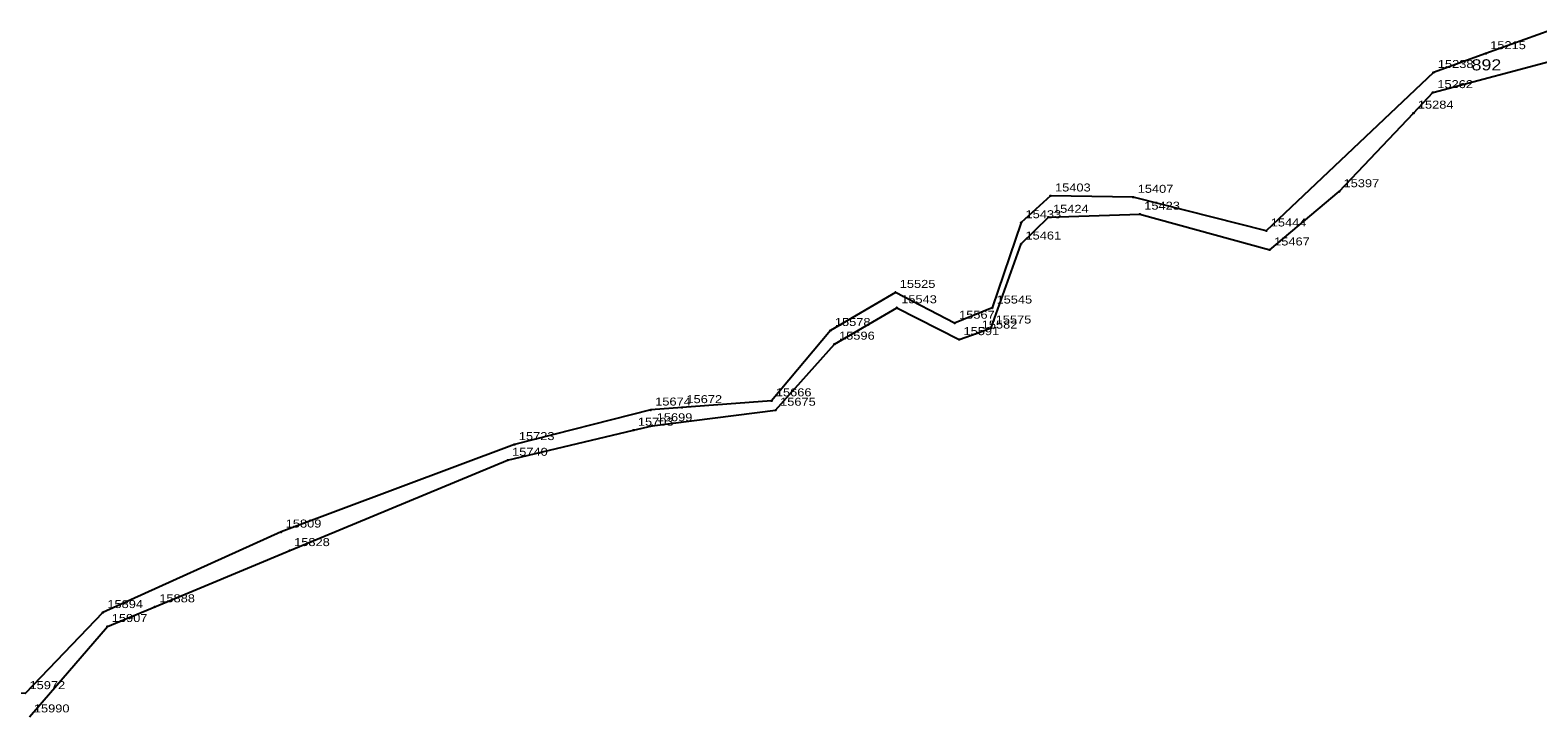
# Model space of a CAD drawing. Extents: x 4640203 to 4641683, y 5358965 to 5360242.
# Drawn here: x 4641223.1 to 4641393, y 5359721.3 to 5359798.7 of the extents above; entities that cross this region are included whole.
import ezdxf

# ---------------------------------------------------------------- set-up
doc = ezdxf.new("R2010")
doc.units = 0
doc.header["$LTSCALE"] = 0.36
doc.layers.add('24', color=7, linetype='Continuous')
for name, color, linetype, lineweight in [('25', 7, 'Continuous', 25), ('27', 7, 'Continuous', 25), ('8', 7, 'Continuous', 25)]:
    doc.layers.add(name, color=color, linetype=linetype, lineweight=lineweight)

msp = doc.modelspace()

# ---------------------------------------------------------------- linework, layer by layer
at = {"layer": '25'}
for points in [[(4641394.42, 5359798.68), (4641387.1, 5359796.04), (4641381.2, 5359793.92), (4641362.38, 5359776.07), (4641347.39, 5359779.86), (4641338.08, 5359780.01), (4641334.76, 5359777), (4641331.49, 5359767.39), (4641327.27, 5359765.68), (4641320.59, 5359769.15), (4641313.28, 5359764.86), (4641306.63, 5359756.94), (4641296.56, 5359756.17), (4641293.04, 5359755.9), (4641277.68, 5359752.01), (4641251.42, 5359742.16), (4641231.33, 5359733.09), (4641222.56, 5359723.96), (4641218.63, 5359724.05), (4641212.42, 5359727.51), (4641209.43, 5359728.75), (4641205.11, 5359734.45), (4641198.05, 5359737.91)], [(4641362.76, 5359773.93), (4641370.58, 5359780.49), (4641378.95, 5359789.34), (4641381.14, 5359791.65), (4641395.53, 5359795.47)], [(4641223.05, 5359721.34), (4641231.83, 5359731.52), (4641237.18, 5359733.74), (4641252.37, 5359740.07), (4641276.92, 5359750.24), (4641291.09, 5359753.63), (4641293.21, 5359754.13), (4641307.11, 5359755.88), (4641313.75, 5359763.32), (4641320.75, 5359767.42), (4641327.77, 5359763.83), (4641329.82, 5359764.57), (4641331.39, 5359765.14), (4641334.75, 5359774.6), (4641337.85, 5359777.61), (4641348.13, 5359777.96), (4641362.76, 5359773.93)]]:
    msp.add_lwpolyline(points, dxfattribs=at)
at = {"layer": '27'}
for points in [[(4641394.42, 5359798.68), (4641387.1, 5359796.04), (4641381.2, 5359793.92), (4641362.38, 5359776.07), (4641347.39, 5359779.86), (4641338.08, 5359780.01), (4641334.76, 5359777), (4641331.49, 5359767.39), (4641327.27, 5359765.68), (4641320.59, 5359769.15), (4641313.28, 5359764.86), (4641306.63, 5359756.94), (4641296.56, 5359756.17), (4641293.04, 5359755.9), (4641277.68, 5359752.01), (4641251.42, 5359742.16), (4641231.33, 5359733.09), (4641222.56, 5359723.96)], [(4641348.13, 5359777.96), (4641362.76, 5359773.93), (4641370.58, 5359780.49), (4641378.95, 5359789.34), (4641381.14, 5359791.65), (4641395.53, 5359795.47)], [(4641223.05, 5359721.34), (4641231.83, 5359731.52), (4641237.18, 5359733.74), (4641252.37, 5359740.07), (4641276.92, 5359750.24), (4641291.09, 5359753.63), (4641293.21, 5359754.13), (4641307.11, 5359755.88), (4641313.75, 5359763.32), (4641320.75, 5359767.42), (4641327.77, 5359763.83), (4641329.82, 5359764.57), (4641331.39, 5359765.14), (4641334.75, 5359774.6), (4641337.85, 5359777.61), (4641348.13, 5359777.96)]]:
    msp.add_lwpolyline(points, dxfattribs=at)
at = {"layer": '8'}
for centre in [(4641387.1, 5359796.04), (4641381.2, 5359793.92), (4641381.14, 5359791.65), (4641378.95, 5359789.34), (4641338.08, 5359780.01), (4641370.58, 5359780.49), (4641347.39, 5359779.86), (4641334.76, 5359777), (4641337.85, 5359777.61), (4641348.13, 5359777.96), (4641362.38, 5359776.07), (4641334.75, 5359774.6), (4641362.76, 5359773.93), (4641320.59, 5359769.15), (4641320.75, 5359767.42), (4641331.49, 5359767.39), (4641313.28, 5359764.86), (4641327.27, 5359765.68), (4641331.39, 5359765.14), (4641313.75, 5359763.32), (4641327.77, 5359763.83), (4641329.82, 5359764.57), (4641296.56, 5359756.17), (4641306.63, 5359756.94), (4641293.04, 5359755.9), (4641307.11, 5359755.88), (4641291.09, 5359753.63), (4641293.21, 5359754.13), (4641277.68, 5359752.01), (4641276.92, 5359750.24), (4641251.42, 5359742.16), (4641252.37, 5359740.07), (4641231.33, 5359733.09), (4641237.18, 5359733.74), (4641231.83, 5359731.52)]:
    msp.add_circle(centre, 0.045, dxfattribs=at)

# ---------------------------------------------------------------- texts
at = {"layer": '24', "width": 1.2}
msp.add_text('892', height=1.25, dxfattribs=at).set_placement((4641385.5, 5359794.15))
at = {"layer": '8', "width": 1.2}
for s, p in [('15215', (4641387.6, 5359796.54)), ('15238', (4641381.7, 5359794.42)), ('15262', (4641381.64, 5359792.15)), ('15284', (4641379.45, 5359789.84)), ('15397', (4641371.08, 5359780.99)), ('15403', (4641338.58, 5359780.51)), ('15407', (4641347.89, 5359780.36)), ('15433', (4641335.26, 5359777.5)), ('15424', (4641338.35, 5359778.11)), ('15423', (4641348.63, 5359778.46)), ('15444', (4641362.88, 5359776.57)), ('15461', (4641335.25, 5359775.1)), ('15467', (4641363.26, 5359774.43)), ('15525', (4641321.09, 5359769.65)), ('15543', (4641321.25, 5359767.92)), ('15545', (4641331.99, 5359767.89)), ('15567', (4641327.77, 5359766.18)), ('15575', (4641331.89, 5359765.64)), ('15578', (4641313.78, 5359765.36)), ('15596', (4641314.25, 5359763.82)), ('15591', (4641328.27, 5359764.33)), ('15582', (4641330.32, 5359765.07)), ('15666', (4641307.13, 5359757.44)), ('15674', (4641293.54, 5359756.4)), ('15672', (4641297.06, 5359756.67)), ('15675', (4641307.61, 5359756.38)), ('15703', (4641291.59, 5359754.13)), ('15699', (4641293.71, 5359754.63)), ('15723', (4641278.18, 5359752.51)), ('15740', (4641277.42, 5359750.74)), ('15809', (4641251.92, 5359742.66)), ('15828', (4641252.87, 5359740.57)), ('15894', (4641231.83, 5359733.59)), ('15888', (4641237.68, 5359734.24)), ('15907', (4641232.33, 5359732.02)), ('15972', (4641223.06, 5359724.46)), ('15990', (4641223.55, 5359721.84))]:
    msp.add_text(s, height=0.9, dxfattribs=at).set_placement(p)

doc.saveas('drawing.dxf')
